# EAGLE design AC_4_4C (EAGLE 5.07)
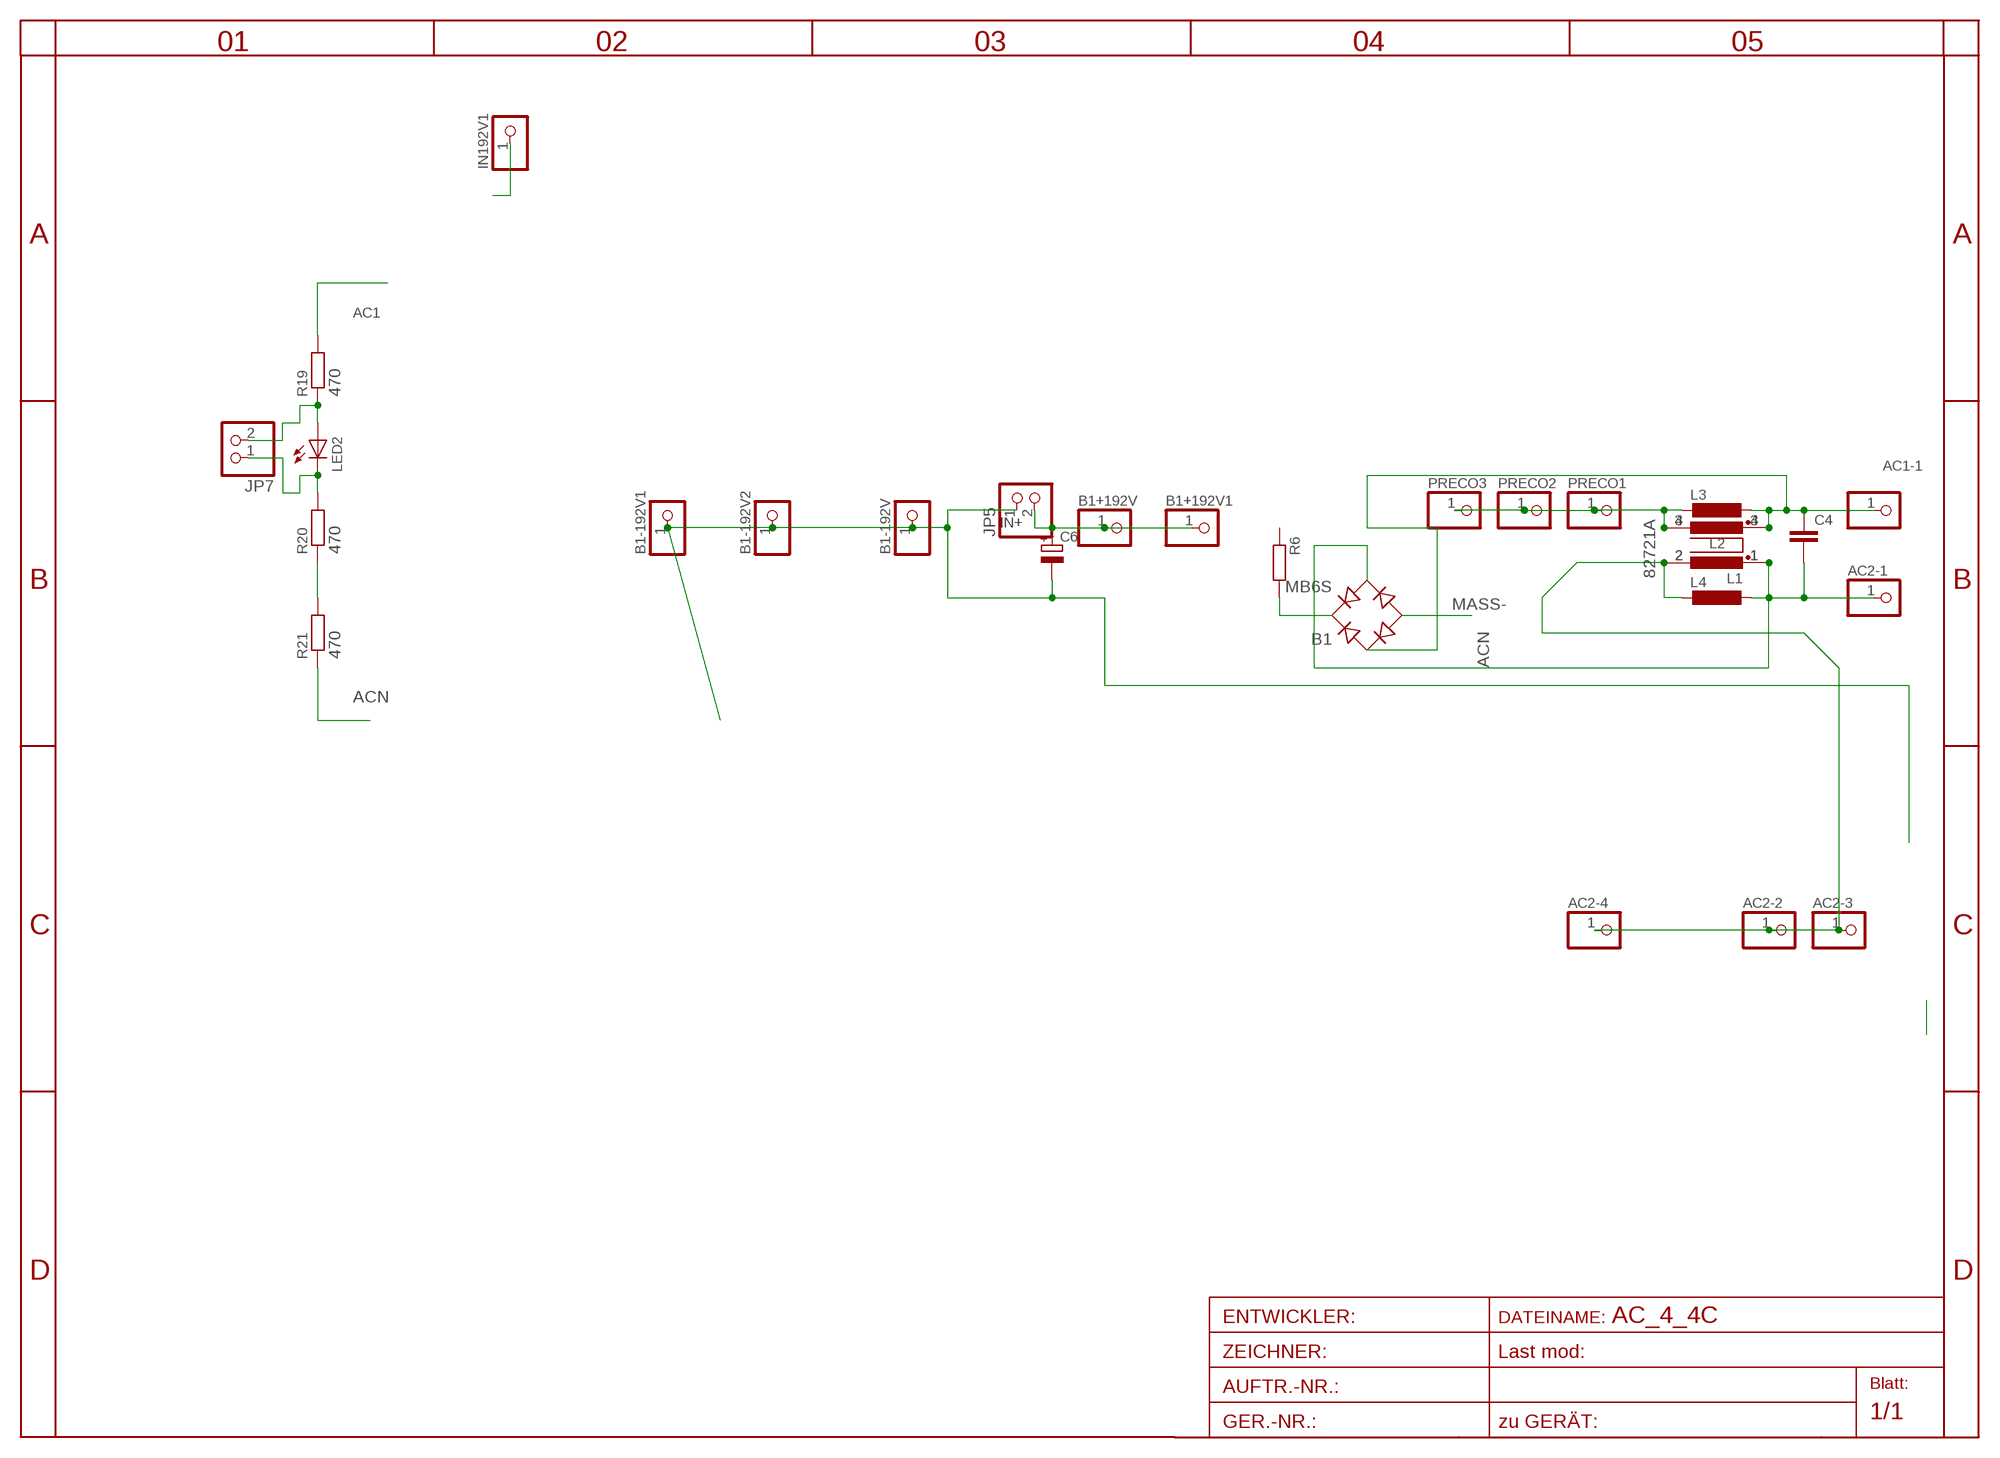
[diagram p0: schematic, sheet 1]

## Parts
AC1-1  PINHD-1X14.5MM  [1X4MM5]
AC2-1  PINHD-1X14.5MM  [1X4MM5]
AC2-2  PINHD-1X13MM2  [1X3MM2]
AC2-3  PINHD-1X13MM2  [1X3MM2]
AC2-4  PINHD-1X12MM3  [1X2MM3]
B1  MB6S  [SOIC-4]
B1+192V  PINHD-1X13MM2  [1X3MM2]
B1+192V1  PINHD-1X13MM2  [1X3MM2]
B1-192V  PINHD-1X13MM2  [1X3MM2]
B1-192V1  PINHD-1X13MM2  [1X3MM2]
B1-192V2  PINHD-1X13MM2  [1X3MM2]
C4  C-EU102_152-062X184  [C102_152-062X184]
C6  CPOL-EUE10-20  [EB20D]
IN192V1  PINHD-1X13MM2  [1X3MM2]
JP5  PINHD-1X2STR  [1X02]
JP7  PINHD-1X2STR  [1X02]
L1  R1405VB1  [B1]
L2  82721A  [82721A]
L3  L-EU2200-15.24  [2200-15.24]
L4  L-EU2200-15.24  [2200-15.24]
LED2  LED3MM  [LED3MM]
PRECO1  PINHD-1X12MM3  [1X2MM3]
PRECO2  PINHD-1X13MM2  [1X3MM2]
PRECO3  PINHD-1X13MM2  [1X3MM2]
R6  R-EU_0207/60  [0207/60]
R19  470  R-EU_0204/5  [0204/5]
R20  470  R-EU_0204/2V  [0204V]
R21  470  R-EU_0204/5  [0204/5]

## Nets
AC1: AC1-1.1 B1.~1(AC1) C4.1 L1.3 L2.4 L3.1 R19.2
ACN: AC2-1.1 B1.~2(AC2) C4.2 L1.1 L2.1 L4.1 R21.1
IN+: B1+192V1.1 B1+192V.1 C6.+ IN192V1.1 JP5.2
INN: AC2-2.1 AC2-3.1 AC2-4.1 L1.2 L2.2 L4.2
MASS-: B1-192V1.1 B1-192V2.1 B1-192V.1 B1.- C6.- JP5.1
N$6: JP7.2 LED2.A R19.1
N$9: JP7.1 LED2.K(C) R20.2
N$13: R20.1 R21.2
N$33: B1.+ R6.2
PRECOIL: L1.4 L2.3 L3.2 PRECO1.1 PRECO2.1 PRECO3.1
Unconnected: R6.1

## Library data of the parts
AC1-1 AC2-1-AC2-4 B1+192V B1+192V1 B1-192V B1-192V1 B1-192V2 IN192V1 PRECO1-PRECO3 = pinhead:PINHD-1X1: PIN HEADER
B1 = rectifier:MB*S: Bridge Rectifier Source: http://www.fairchildsemi.com/ds/MB/MB6S.pdf
C4 = rcl:C-EU: CAPACITOR, European symbol
C6 = rcl:CPOL-EU: POLARIZED CAPACITOR, European symbol
JP5 JP7 = pinhead:PINHD-1X2: PIN HEADER
L1 = inductor-nkl:R1405V: Übertrager (verlustarm) bis typ. 400kHz Power transformer (low loss) up to typ. 400kHz
L2 = inductors:82721A: FILTER
L3 L4 = rcl:L-EU: INDUCTOR, European symbol
LED2 = led:LED: LED
R6 R19-R21 = rcl-2:R-EU_: RESISTOR, European symbol

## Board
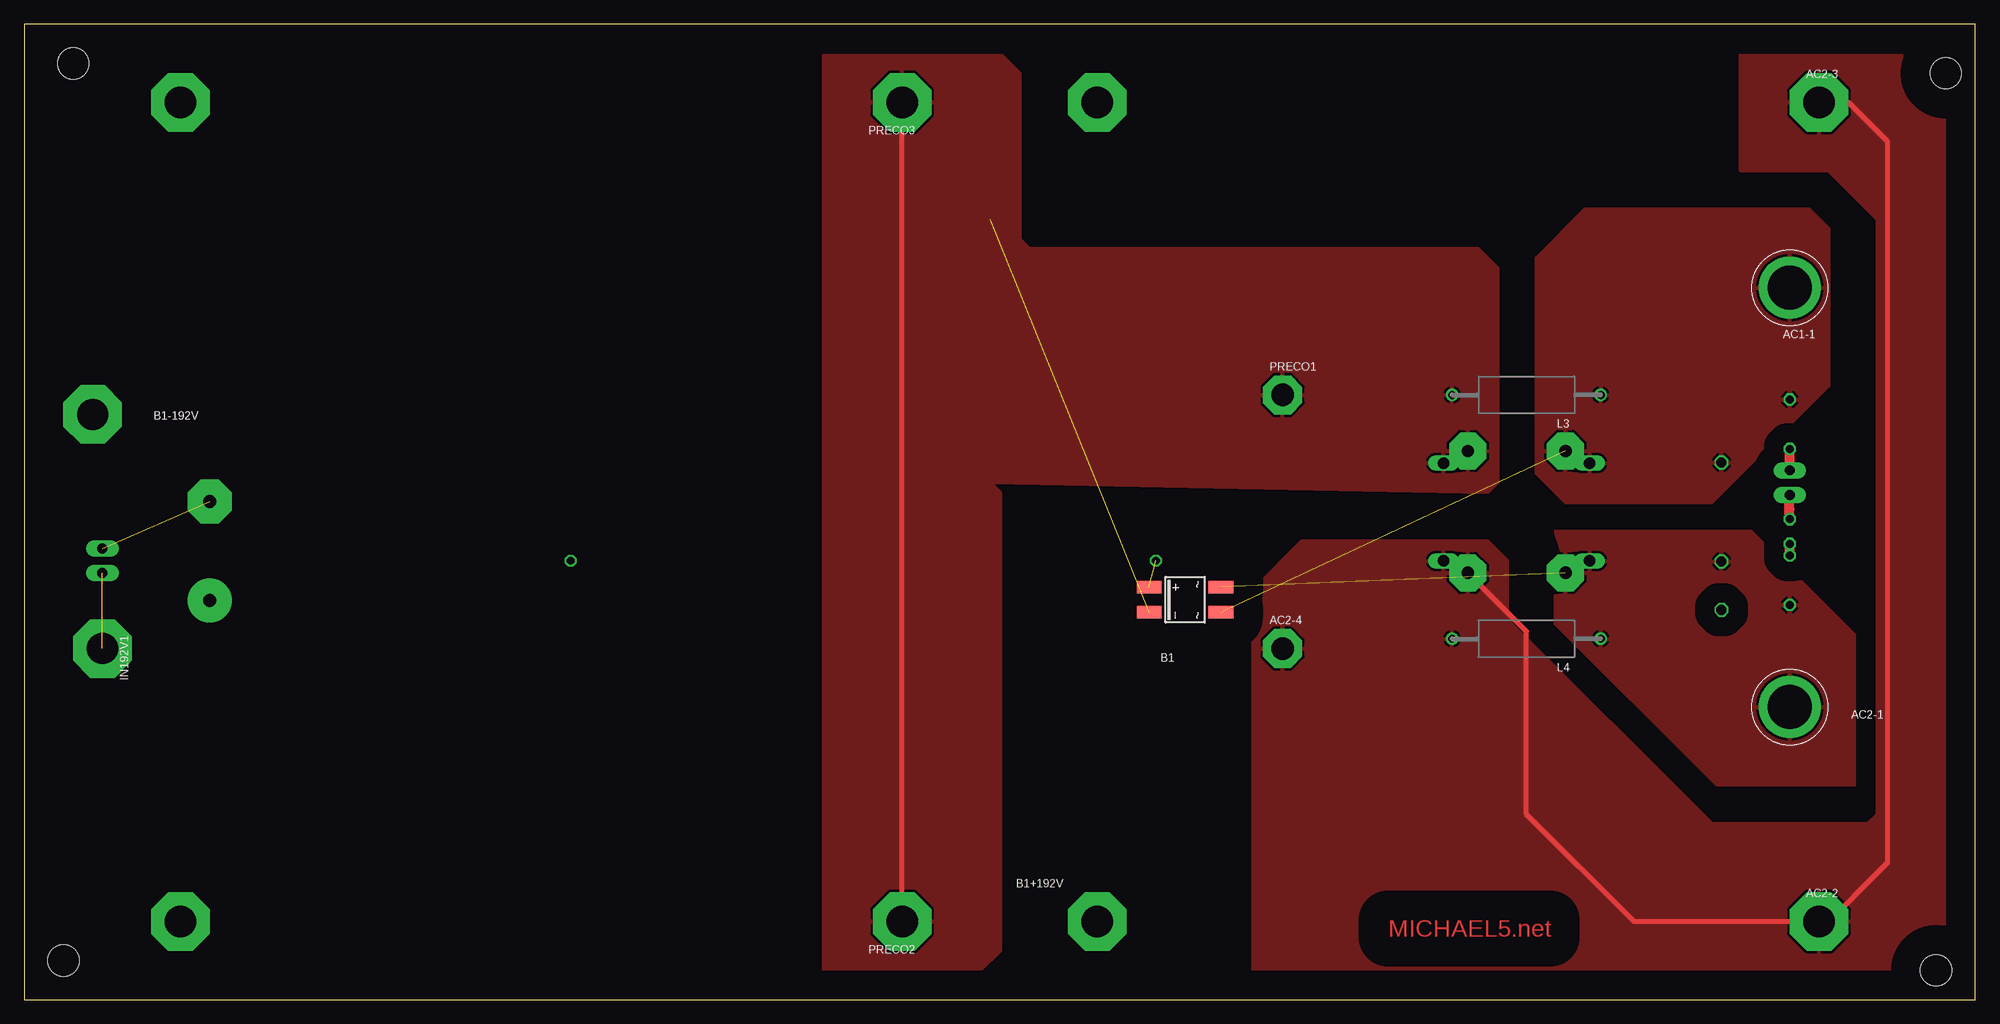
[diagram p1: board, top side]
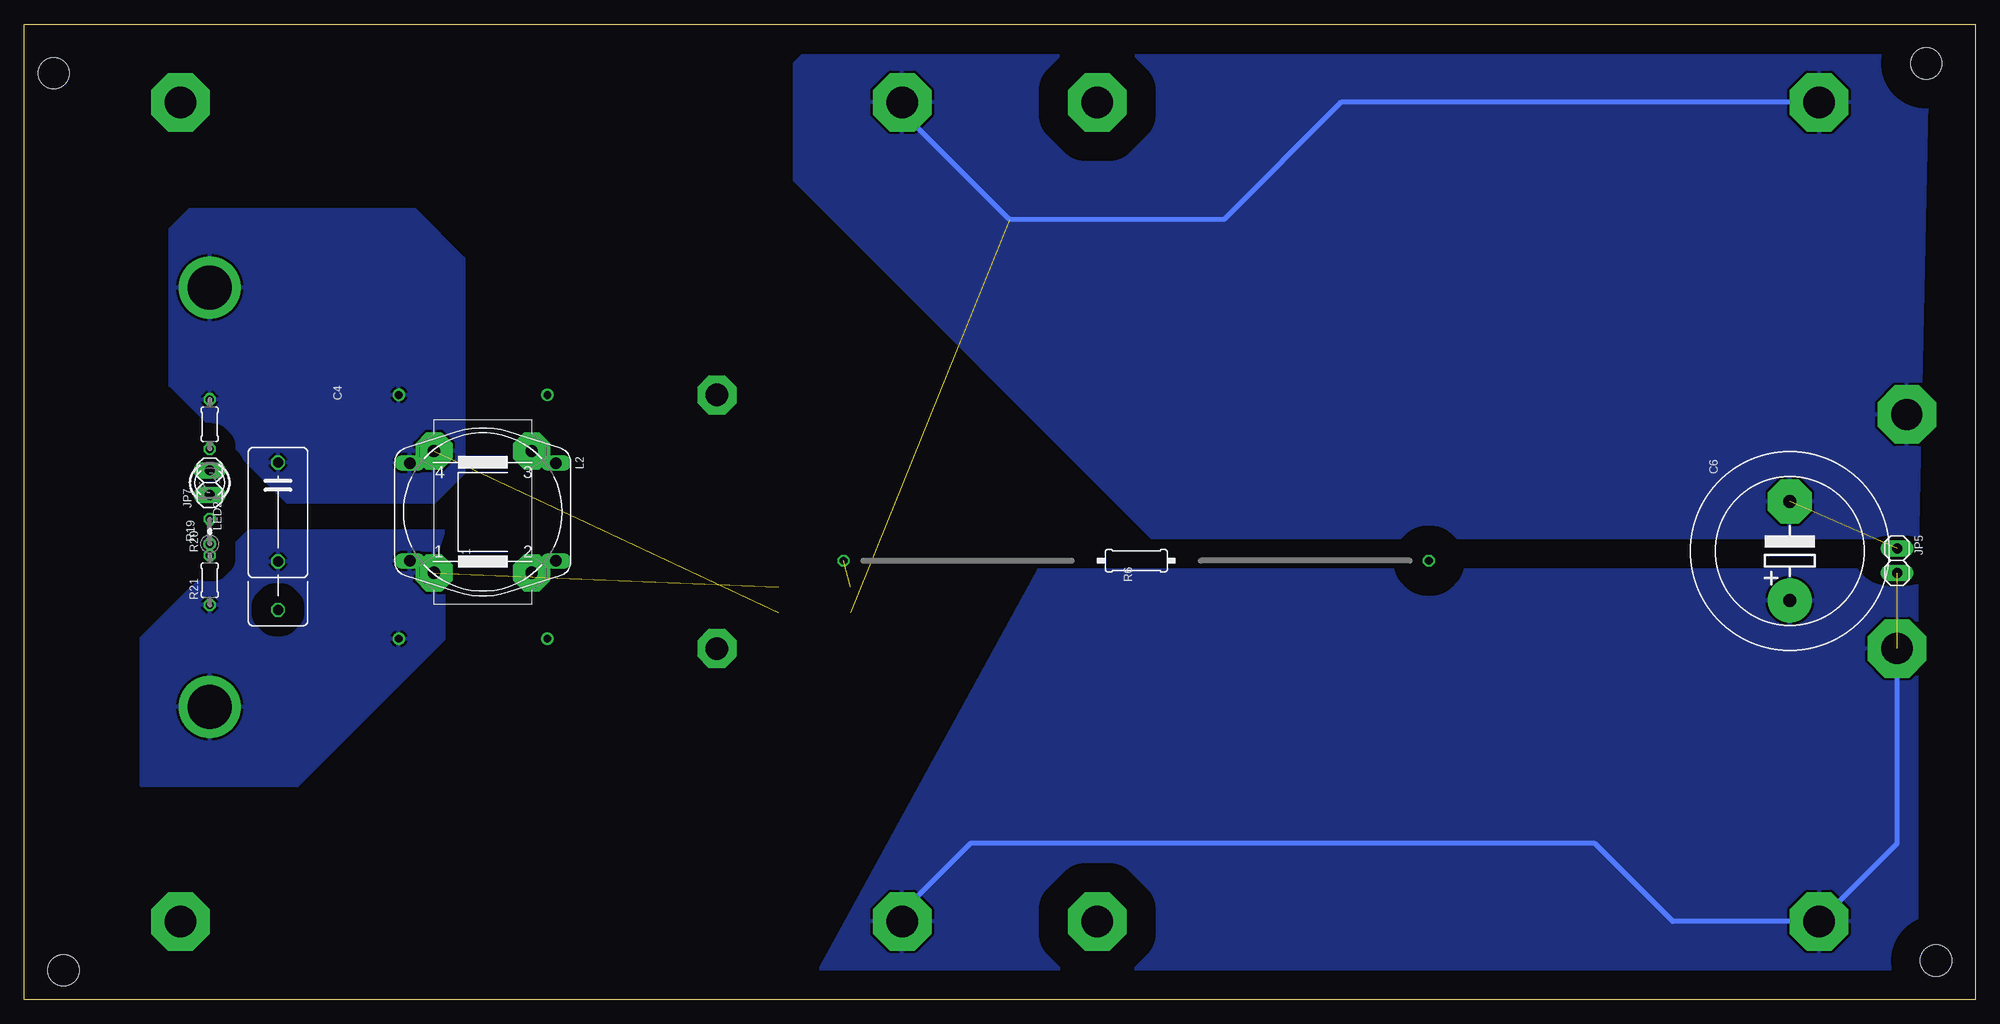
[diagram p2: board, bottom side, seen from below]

Size 200 x 100 mm. Coordinates in mm from the lower left corner, seen from the top.
Outline: 0,0 200,0 200,100 0,100 0,0
Copper layers (1*16): Top 0.035mm / dielectric 1.5mm / Bottom 0.035mm
Design rules "default *": minimum track width 12mil, minimum drill 24mil, track to track 8mil, track to pad 8mil, pad to pad 8mil, via to via 8mil, smd to smd 8mil, copper to edge 40mil, drill to drill 8mil, minimum pad ring 8mil, minimum via ring 8mil, stop-mask expansion 4mil, vias tented up to drill 0mil, thermal gap 10mil
Holes 3.2 mm at 5,96 4,4 197,95 196,3

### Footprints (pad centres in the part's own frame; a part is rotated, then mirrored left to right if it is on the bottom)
1X4MM5 = drill 4.5 pad 6.35 round: 1 0,0
1X3MM2 = drill 3.2 pad 6 octagon: 1 0,0
1X2MM3 = drill 2.3 pad 4 octagon: 1 0,0
SOIC-4 = smd 1.27 x 2.54: + 1.3,3.685; - -1.3,3.685; ~1 -1.3,-3.685; ~2 1.3,-3.685
C102_152-062X184 = drill 1.016 octagon: 1 -5.08,0; 2 5.08,0; 3 10.033,0
EB20D = drill 1.3 pad 4.5 round: + -5.08,0 | drill 1.3 pad 4.5 octagon: - 5.08,0
1X02 = drill 1.016 pad 1.676 long: 1 -1.27,0; 2 1.27,0
B1 = drill 1.27 pad 3.81 octagon: 1 -6.25,5; 2 -6.25,-5; 3 6.25,5; 4 6.25,-5
82721A = drill 1.194 long: 1 7.493,5.004; 2 -7.493,5.004; 3 -7.493,-5.004; 4 7.493,-5.004
2200-15.24 = drill 0.8 pad 1.27 round: 1 -7.62,0; 2 7.62,0
LED3MM = drill 0.8 pad 1.27 octagon: A -1.27,0; K 1.27,0
0207/60 = drill 0.813 octagon: 1 -30,0; 2 30,0
0204/5 = drill 0.8 pad 1.27 octagon: 1 -2.54,0; 2 2.54,0
0204V = drill 0.8 pad 1.27 octagon: 1 -1.27,0; 2 1.27,0

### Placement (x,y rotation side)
AC1-1  181,73 180 top
AC2-1  181,30 180 top
AC2-2  184,8 0 top
AC2-3  184,92 0 top
AC2-4  129,36 0 top
B1  119,41 90 top
B1+192V  110,8 0 top
B1+192V1  16,8 0 top
B1-192V  7,60 180 top
B1-192V1  16,92 180 top
B1-192V2  110,92 0 top
C4  174,50 270 bottom
C6  19,46 90 bottom
IN192V1  8,36 270 top
JP5  8,45 270 bottom
JP7  181,53 90 bottom
L1  153,50 90 bottom
L2  153,50 180 bottom
L3  154,62 180 top
L4  154,37 180 top
LED2  181,53 270 bottom
PRECO1  129,62 0 top
PRECO2  90,8 180 top
PRECO3  90,92 180 top
R6  86,45 180 bottom
R19  181,59 90 bottom
R20  181,48 90 bottom
R21  181,43 90 bottom

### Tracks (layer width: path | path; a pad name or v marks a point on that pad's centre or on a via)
AC1  (1 unrouted)
  pour Bottom (isolate 2): 155,65 155,54 158,51 173,51 185,63 185,79 183,81 160,81 155,76
  pour Top (isolate 2): 155,65 155,54 158,51 173,51 185,63 185,79 183,81 160,81 155,76
ACN  (1 unrouted)
  pour Bottom (isolate 2, rank 2): 157,48 177,48 188,37 188,22 172,22 157,37 157,44 158,45
  pour Top (isolate 2, rank 2): 157,48 177,48 188,37 188,22 172,22 157,37 157,44 158,45
IN+  (1 unrouted)
  Bottom 0.5: B1+192V.1 111,8 103,16 39,16 31,8 B1+192V1.1 8,16 IN192V1.1
  pour Bottom (isolate 3): 6,2 6,43 7,44 96,44 119,2
INN
  Top 0.5: AC2-3.1 187,92 191,88 191,14 184,7 183,8 | L1.2 154,37.75 154,19 165,8 AC2-2.1
  pour Top (isolate 3): 176,97 198,97 198,2 143,2 126,2 126,42 131,47 150,47 152,45 152,39 173,18 189,18 190,19 190,80 185,85 176,85
MASS-  (2 unrouted)
  Bottom 0.5: B1-192V1.1 65,92 77,80 99,80 110,91
  pour Bottom (isolate 3, rank 2): 6,46 83,46 121,84 121,96 120,97 10,97 5,92
N$6
  Top 1.016: JP7.2 R19.1
N$9
  Top 1.016: R20.2 180.96,50.27 JP7.1
N$13
  Top 1.016: R21.2 R20.1
N$33  (1 unrouted)
PRECOIL
  Top 0.5: PRECO2.1 PRECO3.1
  pour Top (isolate 3, rank 2): 82,98 99,98 102,95 102,78 103,77 149,77 151,75 151,53 150,52 99,53 100,52 100,5 98,3 82,3

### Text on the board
Top: MICHAEL5.net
